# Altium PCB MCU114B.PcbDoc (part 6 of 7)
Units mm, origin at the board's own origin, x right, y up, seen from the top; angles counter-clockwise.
Board outline 105.51 x 58.76 mm, 8 copper layers (Top Layer, GND 2, Signal Layer 3, Power 4, Power 5, Signal Layer 6, GND 7, Bottom), stack 1.554 mm thick; 444 components, 418 nets, 1811 pads, 981 vias.
Unrouted connection lines stored in the file: 3.
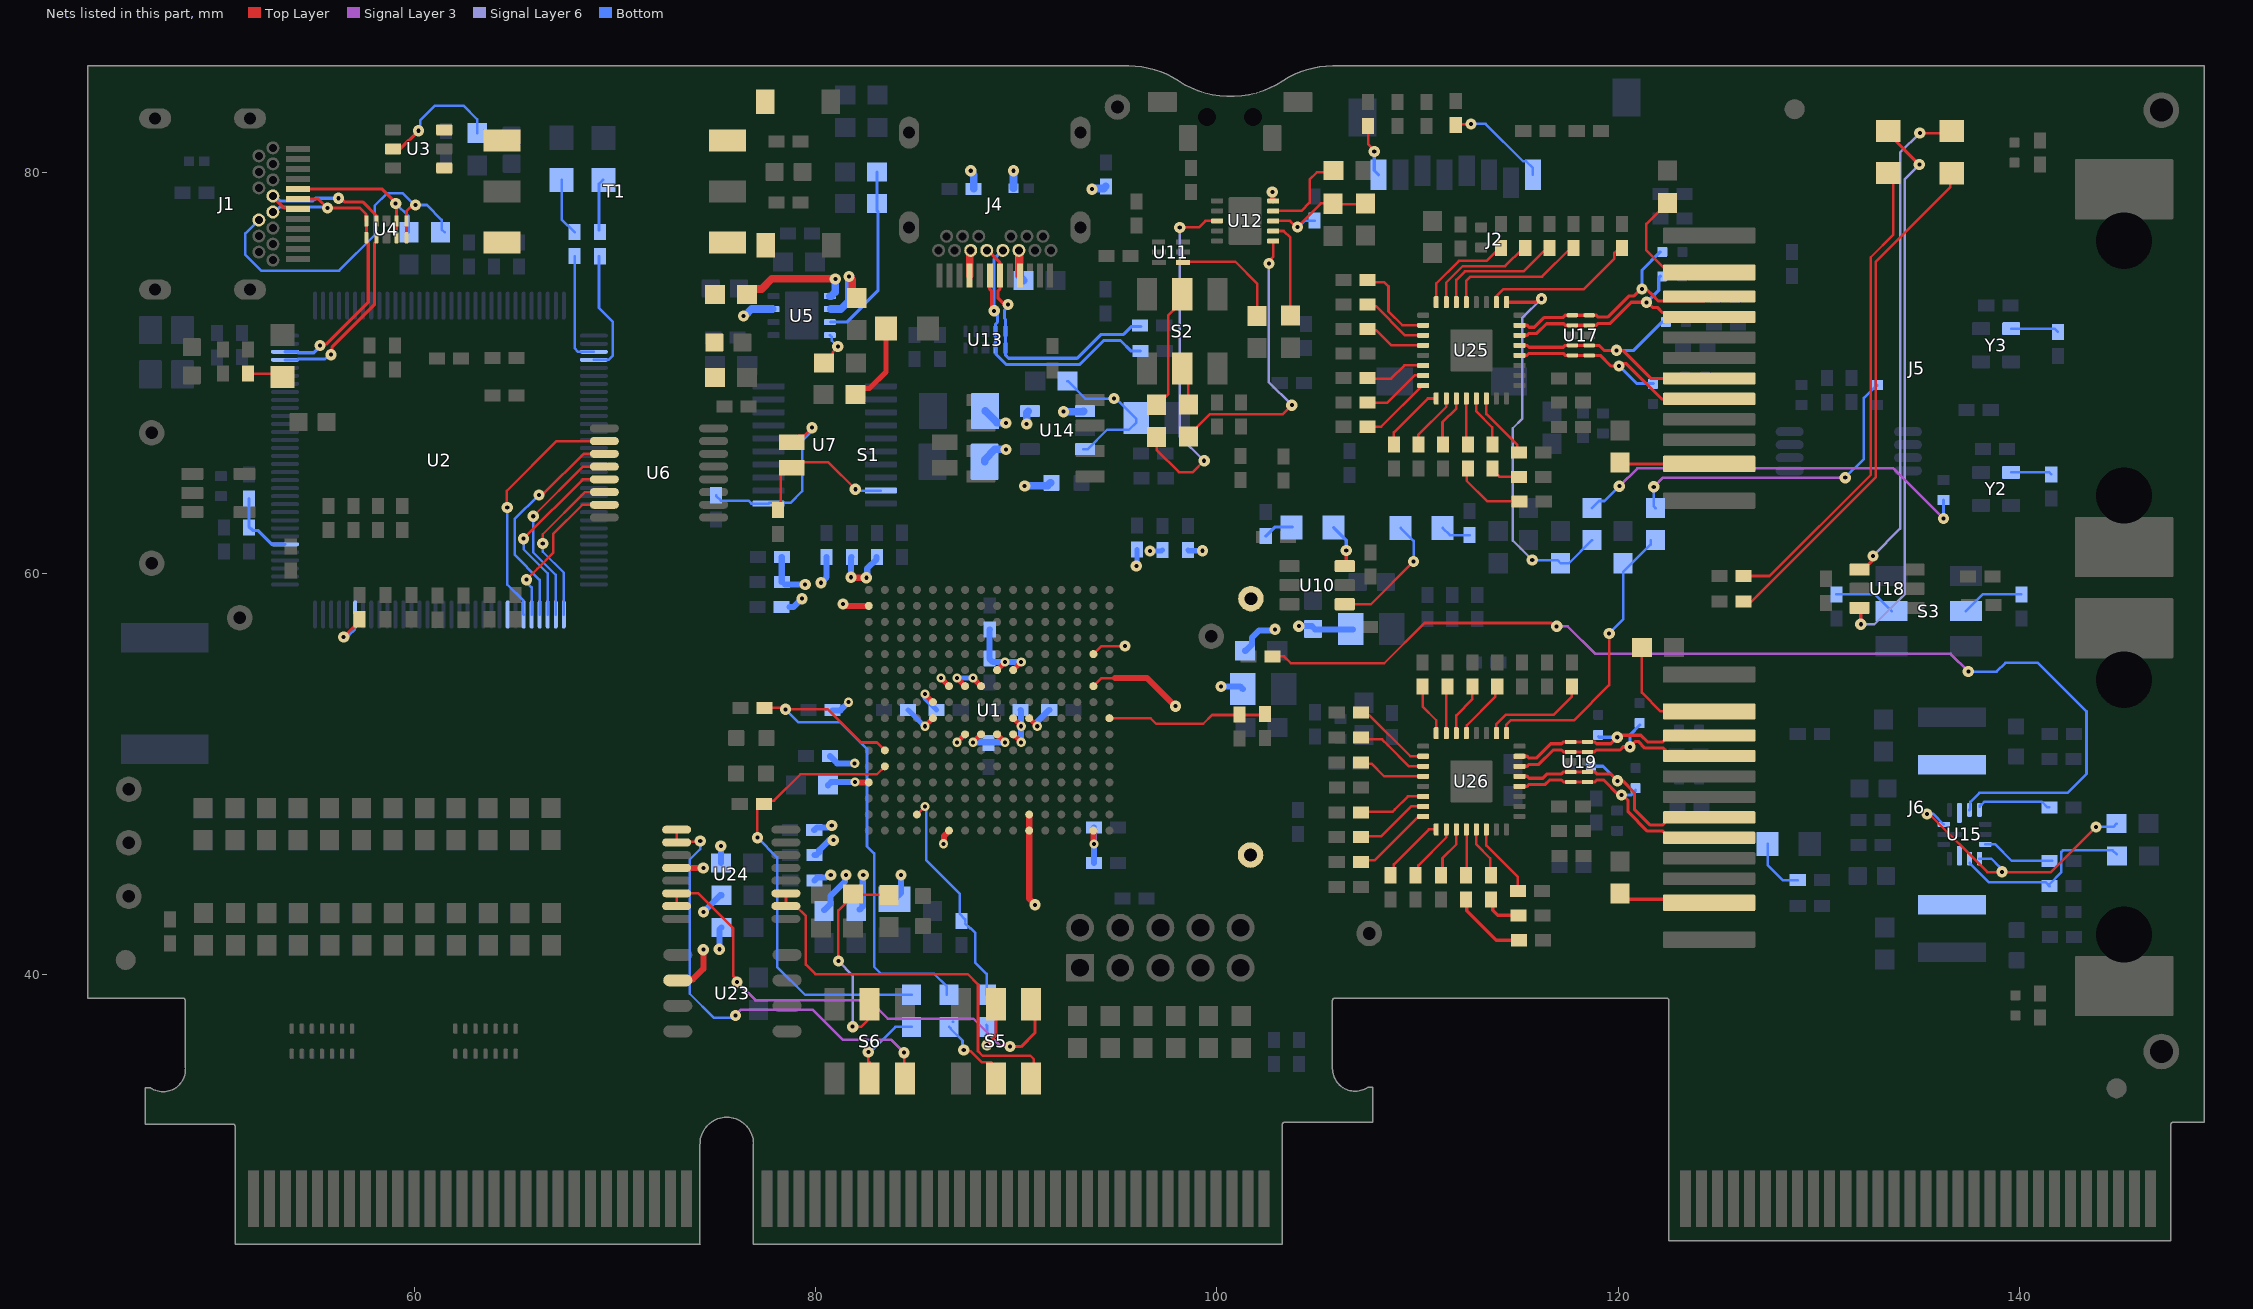
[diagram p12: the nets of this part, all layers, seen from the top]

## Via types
v1: diameter 0.559, hole 0.203, Top Layer to Bottom, tented both sides, 810 vias
v2: diameter 0.457, hole 0.203, Top Layer to Bottom, tented both sides, 153 vias
v3: diameter 0.5, hole 0.2, Top Layer to Bottom, tented both sides, 10 vias
v4: diameter 0.5, hole 0.2, Top Layer to Bottom, tented bottom, 4 vias
v5: diameter 0.5, hole 0.2, Top Layer to Bottom, tented top, 4 vias

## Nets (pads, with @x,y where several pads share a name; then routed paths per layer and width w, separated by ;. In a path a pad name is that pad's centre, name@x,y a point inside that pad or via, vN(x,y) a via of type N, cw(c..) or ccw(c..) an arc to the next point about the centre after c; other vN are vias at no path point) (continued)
NetC122_1: C122.1 R57.1 S6.5 | length 11.1
  Top Layer w0.127: v1(81.128,40.684) 81.128,43.217 81.902,43.99 C122.1@83.359,43.99 ; v1(81.839,37.414) 82.271,37.414 82.557,37.701 82.557,38.485 S6.5@82.689,38.617 ; R57.1@81.864,43.764 R57.1@81.902,43.726 ; C122.1@83.352,44.072 83.359,44.065 C122.1@83.359,43.99 ; C122.1@83.541,43.726 83.359,43.908 C122.1@83.359,43.99 ; C122.1@83.541,43.99 C122.1@83.359,43.99
  Signal Layer 6 w0.127: v1(81.128,40.684) 81.839,39.973 v1(81.839,37.414)
NetD1:A_2: D1:A.2 T1.1
NetD1_2: D1.2 R14.2 | length 1.8
  Top Layer w0.127: R14.2@51.686,69.979 53.242,69.979 D1.2@53.413,69.808
NetD2:A_2: D2:A.2 T1.3
NetD2_2: D2.2 R21.1 | length 4.2
  Top Layer w0.254: R21.1@81.978,68.937 82.284,69.242 82.679,69.242 83.497,70.06 D2.2@83.497,72.228
NetD3_1: D3.1 U10.6 | length 2.2
  Top Layer w0.159: U10.6@106.448,60.368 v1(106.448,61.155)
  Bottom w0.159: D3.1@105.822,62.298 106.448,61.672 v1(106.448,61.155)
NetD3_2: D3.2 R34.2 | length 1.5
  Bottom w0.159: R34.2@102.435,61.876 102.883,62.324 D3.2@103.756,62.324
NetD4_1: D4.1 U10.4 | length 6.3
  Top Layer w0.127: U10.4@106.375,58.478 107.678,58.478 v1(109.804,60.604)
  Bottom w0.127: D4.1@109.156,62.288 109.804,61.64 v1(109.804,60.604)
NetD4_2: D4.2 R35.2 | length 1.5
  Bottom w0.127: D4.2@111.256,62.288 111.617,61.927 R35.2@112.595,61.927
NetD5_1: D5.1 R8.1 | length 2.9
  Bottom w0.127: D5.1@67.332,79.638 67.332,77.671 R8.1@67.973,77.03
NetD6_1: D6.1 R9.1 | length 2.6
  Bottom w0.127: R9.1@69.192,77.13 69.192,79.44 D6.1@69.39,79.638
NetD7_2: D7.2 R94.1 | length 2.9
  Bottom w0.127: D7.2@127.46,46.525 127.46,45.467 128.205,44.721 R94.1@128.96,44.721
NetD8_1: D8.1 U18.6 | length 27.7
  Top Layer w0.159: U18.6@132.037,58.3 132.105,58.232 v1(132.105,57.48) ; D8.1@133.473,82.083 133.473,81.947 v1(135.022,80.398)
  Signal Layer 6 w0.127: v1(132.105,57.48) 132.78,57.48 134.298,58.998 134.298,79.674 v1(135.022,80.398)
NetD8_2: D8.2 R137.1 | length 24.1
  Top Layer w0.127: R137.1@126.265,59.885 127.553,59.885 132.599,64.932 132.599,75.779 133.731,76.911 133.731,79.725 D8.2@133.473,79.983
NetD9_1: D9.1 U18.4 | length 24.8
  Top Layer w0.127: v1(135.048,81.973) 136.542,81.973 D9.1@136.638,82.068
  Top Layer w0.159: U18.4@132.037,60.2 132.237,60.2 132.634,60.598 132.634,60.814 v1(132.711,60.891)
  Signal Layer 6 w0.127: v1(132.711,60.891) 134.07,62.25 134.07,80.995 v1(135.048,81.973)
NetD9_2: D9.2 R138.2 | length 25.9
  Top Layer w0.127: R138.2@126.251,58.615 126.651,58.615 132.859,64.824 132.859,75.557 136.575,79.273 136.575,79.906 D9.2@136.638,79.968
NetJ2_1: J2.1 R37.1 | length 5.1
  Top Layer w0.127: R37.1@111.908,82.363 111.964,82.419 v1(112.669,82.419)
  Bottom w0.127: v1(112.669,82.419) 112.68,82.43 113.4,82.43 115.264,80.566 115.421,80.566 115.757,80.229 J2.1@115.757,79.893
NetJ2_8: J2.8 R43.2 | length 2.6
  Top Layer w0.127: R43.2@107.54,82.323 107.54,81.419 107.844,81.115 v1(107.844,81.058)
  Bottom w0.159: v1(107.844,81.058) 107.844,80.106 J2.8@108.057,79.893
NetJ5_2: J5.2 R135.2 | length 6.4
  Top Layer w0.127: R135.2@122.463,78.494 121.412,77.443 121.412,76.124 122.517,75.018 J5.2@124.544,75.018
NetJ5_11: J5.11 R132.2 | length 4.5
  Top Layer w0.159: R132.2@120.057,65.847 R132.2@120.115,65.905 ; R132.2@120.102,65.537 120.161,65.478 J5.11@124.544,65.478
NetJ6_2: J6.2 R169.2 | length 6
  Top Layer w0.127: R169.2@121.192,56.319 121.192,54.068 122.128,53.132 J6.2@124.544,53.132
NetJ6_11: J6.11 R167.2 | length 4.6
  Top Layer w0.159: R167.2@120.102,44.048 120.38,43.771 124.365,43.771 J6.11@124.544,43.592
NetL1_1: L1.1 U15.6
NetL2_1: L2.1 U15.12
NetR1_1: R1.1 S1.1 U7.1 | length 9.4
  Top Layer w0.127: S1.1@78.8,66.555 79.116,66.871 79.404,66.871 v1(79.814,67.282)
  Bottom w0.127: R1.1@75.034,63.911 75.034,63.876 75.271,63.64 76.644,63.64 76.788,63.496 U7.1@77.642,63.496 77.676,63.531 78.736,63.531 79.324,64.119 79.324,66.623 79.814,67.113 v1(79.814,67.282)
NetR8_2: R8.2 U2.3 | length 5.6
  Bottom w0.127: R8.2@67.973,75.83 67.973,71.245 68.152,71.066 U2.3@68.935,71.066
NetR9_2: R9.2 U2.4 | length 6.3
  Bottom w0.127: U2.4@68.935,70.666 69.657,70.666 69.883,70.891 69.883,72.56 69.192,73.251 R9.2@69.192,75.83
NetR10_1: R10.1 R11.2 U2.70 | length 3.6
  Bottom w0.159: R10.1@51.737,63.756 51.737,62.349 51.928,62.158 52.182,62.158 52.866,61.473 53.528,61.473 U2.70@53.535,61.466
NetR12_2: R12.2 U2.59 | length 2.7
  Top Layer w0.159: v1(56.46,56.852) 56.476,56.852 57.254,57.63 R12.2@57.254,57.73
  Bottom w0.127: v1(56.46,56.852) 56.543,56.935 56.735,56.935 57.022,57.222 57.022,57.952 U2.59@57.035,57.966
NetR18_1: R18.1 U3.5 | length 6.3
  Top Layer w0.159: U3.5@58.925,81.18 59.29,81.18 v1(60.195,82.085)
  Bottom w0.127: v1(60.195,82.085) 60.271,82.161 60.271,82.597 61.012,83.337 62.437,83.337 63.121,82.653 R18.1@63.121,81.964
NetR19_1: R19.1 U5.1 | length 5.7
  Top Layer w0.381: R19.1@76.568,73.914 76.85,74.196 77.308,74.196 77.813,74.701 v1(80.975,74.701)
  Bottom w0.381: U5.1@80.699,73.843 80.768,73.843 80.975,74.05 v1(80.975,74.701)
NetR24_1: R24.1 R26.2 U5.3 | length 8.9
  Bottom w0.159: U5.3@80.75,72.548 81.54,72.548 83.096,74.104 83.096,78.066 83.046,78.116 R24.1@83.046,80.033
NetR25_2: R25.2 U5.4 | length 1.9
  Top Layer w0.127: R25.2@80.404,70.51 80.429,70.51 80.84,70.922 80.84,71.036 81.098,71.293 v1(81.098,71.326)
  Bottom w0.127: U5.4@80.699,71.893 80.711,71.893 80.797,71.806 80.797,71.626 v1(81.098,71.326)
NetR27_2: R27.2 U5.2 | length 3.6
  Top Layer w0.381: v1(81.659,74.818) 81.813,74.664 81.813,73.927 R27.2@82.042,73.698
  Bottom w0.381: U5.2@80.75,73.198 81.238,73.198 81.659,73.618 v1(81.659,74.818)
NetR33_1: R33.1 S2.2 | length 6
  Top Layer w0.127: R33.1@97.039,68.407 97.582,68.95 97.582,72.893 97.836,73.147 97.836,73.499 S2.2@98.273,73.935
NetR33_2: R33.2 U12.3 | length 17.8
  Top Layer w0.127: R33.2@96.998,66.825 96.998,66.171 98.1,65.069 98.8,65.069 v1(99.365,65.634) ; v1(98.146,77.267) 99.101,77.267 99.423,77.589 U12.3@100.008,77.589
  Signal Layer 6 w0.127: v1(98.146,77.267) 98.146,66.853 v1(99.365,65.634)
NetR44_2: R44.2 U11.4 | length 5.8
  Top Layer w0.127: U11.4@98.308,75.529 98.308,75.559 100.914,75.559 102.006,74.467 R44.2@102.006,72.86
NetR46_2: R46.2 R48.2 U1.J16 | length 8.1
  Top Layer w0.127: U1.J16@94.641,52.795 96.691,52.795 96.965,52.521 99.318,52.521 99.754,52.957 102.344,52.957 R46.2@102.387,53
NetR49_2: R49.2 U12.9 | length 4.6
  Top Layer w0.127: U12.9@102.808,78.089 104.212,78.089 104.623,78.5 104.623,79.649 104.991,80.017 R49.2@105.901,80.017
NetR52_1: R52.1 U12.6 | length 14.6
  Top Layer w0.127: R52.1@98.6,66.832 98.6,66.909 99.635,67.945 103.276,67.945 v1(103.734,68.402) ; v1(102.591,75.463) 102.591,75.58 102.808,75.798 U12.6@102.808,76.589
  Signal Layer 6 w0.127: v1(102.591,75.463) 102.583,75.456 102.583,69.553 v1(103.734,68.402)
NetR52_2: R52.2 S2.5 | length 1.9
  Top Layer w0.127: S2.5@98.273,70.235 98.577,69.93 R52.2@98.577,68.44
NetR53_1: R53.1 U15.4 U15.10 | length 14.4
  Top Layer w0.127: v1@135.241,48.023 v1(135.403,48.023) 135.517,48.023 138.417,45.124 141.582,45.124 v1(143.836,47.378)
  Bottom w0.127: v1(135.403,48.023) 135.719,48.023 U15.10@136.235,47.507 ; U15.4@138.023,45.795 138.608,45.795 138.999,45.404 138.999,45.395 139.27,45.124 v1@139.279,45.124 ; v1(143.836,47.378) 144.694,47.378 R53.1@144.855,47.539
  other v1: 139.141,45.136
NetR55_2: R55.2 R61.1 R78.2 U12.8 | length 6.2
  Top Layer w0.127: U12.8@102.808,77.589 103.645,77.589 103.942,77.292 v1(104.013,77.292) 105.183,78.462 R78.2@105.835,78.462 ; R78.2@105.871,78.429 R55.2@107.471,78.429
  Bottom w0.127: v1(104.013,77.292) 104.084,77.292 104.381,77.589 104.859,77.589 R61.1@104.877,77.607
NetR58_1: R58.1 U25.23 | length 3.4
  Top Layer w0.127: R58.1@107.494,68.53 108.503,68.53 109.861,69.887 U25.23@110.285,69.887
NetR62_2: R62.2 S3.2 | length 3.1
  Bottom w0.127: S3.2@137.345,58.133 138.181,58.969 R62.2@140.106,58.969
NetR63_2: R63.2 S3.5 | length 3.1
  Bottom w0.127: R63.2@130.885,58.969 132.808,58.969 S3.5@133.645,58.133
NetR69_1: R69.1 Y2.1 | length 2
  Bottom w0.127: Y2.1@139.602,65.054 141.502,65.054 R69.1@141.601,64.955
NetR76_1: R76.1 Y3.1 | length 2.4
  Bottom w0.127: Y3.1@139.602,72.216 141.772,72.216 R76.1@141.931,72.057
NetR82_1: R82.1 U15.13 | length 53.7
  Top Layer w0.127: R82.1@102.78,55.88 103.35,55.88 103.693,55.537 108.344,55.537 110.35,57.544 116.66,57.544 116.825,57.379 v1(116.942,57.379)
  Signal Layer 3 w0.127: v1(116.942,57.379) 117.494,57.379 118.866,56.007 125.891,56.007 125.897,56.001 126.265,56.001 126.271,56.007 136.576,56.007 v1(137.465,55.118)
  Bottom w0.127: v1(137.465,55.118) 138.877,55.118 139.317,55.558 140.937,55.558 143.358,53.136 143.358,50.013 142.418,49.073 138.017,49.073 137.568,48.623 137.568,48.265 U15.13@137.523,48.22
NetR83_1: R83.1 U25.27 | length 2.6
  Top Layer w0.127: R83.1@111.247,66.454 111.247,67.559 111.935,68.247 U25.27@111.935,68.737
NetR84_1: R84.1 U25.26 | length 2.9
  Top Layer w0.127: R84.1@110.036,66.454 110.036,66.916 111.435,68.315 U25.26@111.435,68.737
NetR86_1: R86.1 U25.25 | length 3.4
  Top Layer w0.127: R86.1@108.825,66.454 108.825,67.042 110.52,68.737 U25.25@110.935,68.737
NetR87_1: R87.1 U25.24 | length 3.6
  Top Layer w0.127: R87.1@107.494,67.327 108.19,67.327 110.25,69.387 U25.24@110.285,69.387
NetR91_1: R91.1 U26.23 | length 3.7
  Top Layer w0.127: R91.1@107.161,46.917 108.201,46.917 108.325,47.041 109.683,48.399 U26.23@110.285,48.399
NetR92_1: R92.1 U26.27 | length 2.6
  Top Layer w0.127: R92.1@111.247,44.966 111.247,45.823 111.935,46.511 U26.27@111.935,47.249
NetR97_1: R97.1 U15.3 | length 3.7
  Bottom w0.127: U15.3@138.31,46.507 138.811,46.507 139.632,45.687 R97.1@141.658,45.687
NetR100_1: R100.1 S1.2 U7.19 | length 8.8
  Top Layer w0.127: R100.1@78.105,63.186 78.261,63.341 78.261,64.968 78.293,65.001 78.336,65.001 78.62,65.285 S1.2@78.8,65.285 78.685,65.285 78.653,65.252 S1.2@78.369,64.968 ; S1.2@78.302,65.039 78.584,65.321 78.817,65.554 80.628,65.554 v1(81.971,64.211)
  Bottom w0.127: v1(81.971,64.211) 82.036,64.146 U7.19@83.242,64.146
NetR103_1: R103.1 R104.2 U15.5 | length 9.2
  Bottom w0.127: U15.5@137.528,45.577 138.477,44.628 141.31,44.628 141.464,44.474 R103.1@141.513,44.425 ; R103.1@141.508,44.518 142.108,45.118 142.108,46.135 142.183,46.209 144.663,46.209 R104.2@144.855,46.017
NetR109_2: R109.2 U25.10 | length 7.6
  Top Layer w0.127: U25.10@113.935,73.537 113.935,73.84 114.27,74.175 118.284,74.175 119.821,75.712 119.821,76.001 R109.2@120.036,76.216
NetR110_1: R110.1 U26.26 | length 2.9
  Top Layer w0.127: R110.1@110.044,44.966 110.044,45.458 111.435,46.85 U26.26@111.435,47.249
NetR114_2: R114.2 U25.19 | length 3.4
  Top Layer w0.127: R114.2@107.494,73.339 107.934,73.339 109.385,71.887 U25.19@110.285,71.887
NetR115_2: R115.2 U25.18 | length 4.4
  Top Layer w0.127: R115.2@107.494,74.541 108.342,74.541 108.556,74.327 108.556,73.082 109.251,72.387 U25.18@110.285,72.387
NetR116_2: R116.2 U25.15 | length 5.5
  Top Layer w0.127: U25.15@111.435,73.537 111.435,74.515 112.257,75.337 114.373,75.337 R116.2@115.252,76.216
NetR117_2: R117.2 U25.14 | length 6.3
  Top Layer w0.127: U25.14@111.935,73.537 111.935,74.647 112.365,75.077 115.295,75.077 R117.2@116.435,76.216
NetR118_2: R118.2 U25.13 | length 6.9
  Top Layer w0.127: U25.13@112.435,73.537 112.435,74.614 112.638,74.816 116.218,74.816 R118.2@117.618,76.216
NetR119_2: R119.2 U25.20 | length 3.1
  Top Layer w0.127: R119.2@107.494,72.136 107.949,72.136 108.698,71.387 U25.20@110.285,71.387
NetR120_2: R120.2 U25.22 | length 3.1
  Top Layer w0.127: R120.2@107.494,69.732 108.689,69.732 109.345,70.387 U25.22@110.285,70.387
NetR121_1: R121.1 R123.2 | length 3.6
  Top Layer w0.127: R121.1@112.458,65.254 112.458,64.634 113.473,63.619 R123.2@115.006,63.619
NetR121_2: R121.2 U25.28 | length 2.3
  Top Layer w0.127: U25.28@112.435,68.737 112.435,66.477 R121.2@112.458,66.454
NetR122_1: R122.1 R124.2 | length 1.5
  Top Layer w0.127: R122.1@113.669,65.254 114.085,64.838 R124.2@114.981,64.838
NetR122_2: R122.2 U25.29 | length 2.6
  Top Layer w0.127: U25.29@112.935,68.737 112.935,68.093 113.727,67.302 113.727,66.512 R122.2@113.669,66.454
NetR125_2: R125.2 U25.30 | length 3.3
  Top Layer w0.127: U25.30@113.435,68.737 113.435,67.959 114.787,66.607 114.981,66.414 R125.2@114.981,66.057
NetR126_2: R126.2 U25.16 | length 4.8
  Top Layer w0.127: U25.16@110.935,73.537 110.935,74.472 112.061,75.597 113.45,75.597 R126.2@114.069,76.216
NetR143_2: R143.2 U26.10 | length 5.3
  Top Layer w0.127: U26.10@113.935,52.049 113.935,52.504 114.397,52.966 116.785,52.966 117.699,53.88 R143.2@117.699,54.372
NetR144_1: R144.1 U26.25 | length 3.4
  Top Layer w0.127: R144.1@108.825,44.966 108.827,44.968 108.827,45.511 110.565,47.249 U26.25@110.935,47.249
NetR148_2: R148.2 U26.19 | length 3.7
  Top Layer w0.127: R148.2@107.161,51.736 108.237,51.736 108.517,51.455 109.573,50.399 U26.19@110.285,50.399
NetR149_2: R149.2 U26.18 | length 4
  Top Layer w0.127: R149.2@107.161,52.94 107.606,52.94 109.648,50.899 U26.18@110.285,50.899
NetR150_2: R150.2 U26.15 | length 2.3
  Top Layer w0.127: U26.15@111.435,52.049 111.435,54.31 R150.2@111.497,54.372
NetR151_1: R151.1 U26.30 | length 3.7
  Top Layer w0.127: U26.30@113.435,47.224 113.435,46.447 115.006,44.876 R151.1@115.006,44.188
NetR152_2: R152.2 U26.14 | length 2.7
  Top Layer w0.127: U26.14@111.935,52.049 111.935,52.94 112.738,53.743 R152.2@112.738,54.372
NetR153_2: R153.2 U26.13 | length 3
  Top Layer w0.127: U26.13@112.435,52.049 112.457,52.071 112.457,52.438 113.876,53.856 113.876,54.27 R153.2@113.978,54.372
NetR154_2: R154.2 U26.20 | length 3.4
  Top Layer w0.127: R154.2@107.161,50.531 107.711,50.531 108.339,49.903 110.281,49.903 U26.20@110.285,49.899
NetR155_2: R155.2 U26.22 | length 3.4
  Top Layer w0.127: R155.2@107.161,48.122 108.745,48.122 108.867,48.244 109.522,48.899 U26.22@110.285,48.899
NetR156_1: R156.1 R159.2 | length 3.8
  Top Layer w0.159: R156.1@112.458,43.766 112.458,43.196 113.93,41.724 R159.2@115.057,41.724
NetR156_2: R156.2 U26.28 | length 2.3
  Top Layer w0.127: U26.28@112.435,47.249 112.458,47.227 R156.2@112.458,44.966
NetR157_1: R157.1 R160.2 | length 2
  Top Layer w0.159: R157.1@113.669,43.766 113.754,43.68 113.754,43.221 114.006,42.969 R160.2@115.032,42.969
NetR157_2: R157.2 U26.29 | length 2.6
  Top Layer w0.127: U26.29@112.935,47.249 112.935,46.503 113.625,45.814 113.625,45.01 R157.2@113.669,44.966
NetR158_2: R158.2 U26.16 | length 2.6
  Top Layer w0.127: R158.2@110.257,54.372 110.257,53.373 110.935,52.694 U26.16@110.935,52.049
NetR171_2: R171.2 U15.14 | length 3.7
  Bottom w0.127: U15.14@138.024,48.384 138.024,48.434 138.084,48.494 138.134,48.494 138.277,48.637 141.125,48.637 141.408,48.354 R171.2@141.508,48.354
NetR196_1: R196.1 S6.2 | length 4.7
  Top Layer w0.127: v1(82.62,36.152) 82.62,34.986 82.689,34.917 82.689,35.65
  Bottom w0.127: v1(82.62,36.152) 82.718,36.152 83.974,37.408 R196.1@84.781,37.408
NetR196_2: R196.2 R199.2 U1.M2 | length 22.8
  Top Layer w0.127: v1(77.089,46.838) 77.089,48.278 77.325,48.514 R199.2@77.41,48.514 77.586,48.69 77.926,48.69 79.236,50.001 83.047,50.001 U1.M2@83.441,50.395
  Bottom w0.127: v1(77.089,46.838) 78.077,45.85 78.077,40.397 79.465,39.008 R196.2@84.781,39.008
NetR197_1: R197.1 S5.5 | length 3.4
  Top Layer w0.155: v1(88.534,36.507) 88.986,36.959 88.986,38.422 S5.5@89.181,38.617
  Bottom w0.155: R197.1@88.515,37.492 88.534,37.473 v1(88.534,36.507)
NetR197_2: R197.2 R200.2 U1.R4 | length 11.1
  Top Layer w0.127: U1.R4@85.041,47.995 v2(85.441,48.395)
  Bottom w0.127: v2(85.441,48.395) 85.498,48.338 85.498,45.72 87.169,44.05 87.169,43.049 87.448,42.769 R200.2@87.448,42.669 ; R200.2@87.448,42.569 87.684,42.333 87.71,42.333 87.956,42.087 87.956,40.924 87.956,40.6 88.515,40.042 R197.2@88.515,39.008
NetR198_1: R198.1 S5.2 | length 4
  Top Layer w0.127: v1(87.376,36.246) 87.434,36.188 87.729,36.188 88.264,35.653 88.744,35.653 89.181,35.217 S5.2@89.181,34.917
  Bottom w0.127: R198.1@86.648,37.408 86.718,37.338 86.718,37.313 87.316,36.716 87.316,36.306 v1(87.376,36.246) ; R198.1@86.836,37.658 R198.1@86.842,37.653
NetR198_2: R198.2 R201.2 U1.L2 | length 27.2
  Top Layer w0.127: R201.2@77.439,53.308 78.399,53.308 78.469,53.238 80.598,53.238 82.251,51.585 83.051,51.585 U1.L2@83.441,51.195
  Bottom w0.127: v1(78.486,53.238) 79.14,52.585 81.231,52.585 82.553,51.263 82.553,46.403 82.906,46.05 82.906,40.405 83.255,40.056 85.905,40.056 86.534,39.427 R198.2@86.534,39.008
NetR203_1: R203.1 U26.24 | length 4
  Top Layer w0.127: R203.1@107.161,45.712 107.86,45.712 108.52,46.372 110.046,47.899 U26.24@110.285,47.899
NetR212_2: R212.2 U12.7 | length 4.9
  Top Layer w0.127: U12.7@102.808,77.089 103.327,77.089 103.658,76.758 R212.2@103.658,72.867
NetS5_3: S5.3 U24.10 U24.11 | length 20.4
  Top Layer w0.127: U24.11@78.514,44.063 U24.10@78.514,43.428 79.001,43.428 79.501,42.928 79.501,40.514 79.976,40.039 87.578,40.039 88.089,39.528 88.089,36.193 88.316,35.966 90.703,35.966 90.878,35.792 S5.3@90.878,34.97
NetS5_6: S5.6 U24.6 U24.7 | length 25
  Top Layer w0.127: U24.7@73.064,43.428 U24.6@73.064,44.063 74.151,44.063 75.895,42.319 75.895,39.94 76.073,39.762 v1(76.073,39.649) ; U24.7@73.09,43.352 U24.7@73.09,43.428
  Top Layer w0.159: v1(89.687,36.424) 90.238,36.424 90.931,37.116 S5.6@90.931,38.617
  Signal Layer 3 w0.127: v1(76.073,39.649) 76.987,38.735 82.677,38.735 83.601,37.811 87.858,37.811 89.218,36.451 89.66,36.451 v1(89.687,36.424)
NetS6_3: S6.3 U24.1 U24.2 | length 23.2
  Top Layer w0.127: U24.1@73.064,47.238 U24.2@73.064,46.603 73.096,46.635 74.208,46.635 v1(74.239,46.667) ; S6.3@84.244,34.85 84.404,35.01 v1(84.404,36.119)
  Signal Layer 3 w0.127: v1(75.993,37.98) 76.279,38.266 79.663,38.266 79.664,38.266 79.844,38.266 81.356,36.754 83.769,36.754 v1(84.404,36.119)
  Bottom w0.127: v1(74.239,46.667) 74.239,46.27 73.717,45.748 73.717,39.059 74.923,37.852 75.748,37.852 75.876,37.98 v1(75.993,37.98)
NetT1_4: T1.4 U3.3
NetT1_6: T1.6 U3.1
PHY0_25MHZ_CLK: R60.2 R67.2 | length 20.3
  Signal Layer 3 w0.132: v1(120.066,64.364) 120.959,65.257 133.73,65.257 v1(136.231,62.755)
  Bottom w0.132: R60.2@118.706,63.276 119.053,63.623 119.325,63.623 v1(120.066,64.364) ; v1(136.231,62.755) R67.2@136.231,63.678
PHY0_CLK: R59.2 R60.1 U25.9 | length 19.4
  Top Layer w0.159: U25.9@114.435,73.537 115.898,73.537 116.071,73.711 v1(116.18,73.711)
  Signal Layer 6 w0.127: v1(115.722,60.681) 114.75,61.653 114.75,67.254 115.234,67.738 115.234,72.765 v1(116.18,73.711)
  Bottom w0.127: v1(115.722,60.681) 116.982,60.681 R59.2@117.142,60.521 117.551,60.521 R60.1@118.706,61.676
PHY0_RD_N: C93.1 J5.8 U17.5 U17.6 U25.4 | length 12.6
  Top Layer w0.157: U25.4@115.085,70.887 115.462,70.887 115.559,70.985 117.269,70.985 117.367,70.887 U17.5@117.725,70.887 U17.6@118.56,70.887 119.115,70.887 119.645,70.357 v1(120.051,70.357) ; v1@120.043,70.434 120.086,70.477 120.407,70.477 122.165,68.718 J5.8@124.544,68.718
  Bottom w0.157: v1(120.051,70.357) 120.927,69.482 C93.1@121.754,69.482
PHY0_RD_P: C94.1 J5.7 U17.4 U17.7 U25.5 | length 13.2
  Top Layer w0.157: U25.5@115.085,71.387 115.462,71.387 115.559,71.29 117.269,71.29 117.367,71.387 U17.4@117.725,71.387 U17.7@118.56,71.387 119.053,71.387 119.303,71.137 v1(119.924,71.137) 120.231,71.137 121.63,69.738 J5.7@124.544,69.738
  Bottom w0.157: v1(119.924,71.137) 120.78,71.137 121.964,72.321 122.185,72.542 C94.1@122.285,72.542
PHY0_TD_N: C91.1 J5.4 U17.2 U17.9 U25.6 | length 12.1
  Top Layer w0.157: U25.6@115.085,71.887 115.464,71.887 115.559,71.982 115.952,71.982 116.431,72.461 117.291,72.461 117.364,72.387 U17.2@117.725,72.387 U17.9@118.56,72.387 118.922,72.387 119.017,72.482 119.61,72.482 120.659,73.532 v1(121.426,73.532) 121.466,73.532 121.719,73.279 121.954,73.279 122.208,73.025 124.318,73.025 J5.4@124.544,72.798
  Bottom w0.157: v1(121.426,73.532) 122.029,74.134 122.029,74.75 C91.1@122.107,74.828
PHY0_TD_P: C92.1 J5.3 U17.1 U17.10 U25.7 | length 13.2
  Top Layer w0.157: U25.7@115.085,72.387 115.464,72.387 115.559,72.292 115.824,72.292 116.303,72.771 117.248,72.771 117.364,72.887 U17.1@117.725,72.887 U17.10@118.56,72.887 118.922,72.887 119.017,72.792 119.482,72.792 120.531,73.842 120.777,73.842 121.125,74.189 v1(121.193,74.189) 121.419,74.189 121.724,73.884 122.016,73.592 124.318,73.592 J5.3@124.544,73.818
  Bottom w0.157: v1@121.028,74.033 v1@121.188,74.194 ; v1(121.193,74.189) 121.193,75.133 C92.1@122.107,76.048
PHY1_25MHZ_CLK: R66.2 R68.2 | length 16.1
  Signal Layer 3 w0.132: v1(121.782,64.334) 122.238,64.79 v1(131.328,64.79)
  Bottom w0.132: v1(121.782,64.334) 121.782,63.358 R66.2@121.869,63.271 ; v1(131.328,64.79) 132.258,65.72 132.258,68.76 R68.2@132.904,69.406 R68.2@132.923,69.387
PHY1_CLK: R64.2 R66.1 U26.9 | length 14.5
  Top Layer w0.127: U26.9@114.435,52.049 114.435,52.479 114.661,52.705 117.819,52.705 119.558,54.443 v1(119.558,57.023)
  Bottom w0.127: v1(119.558,57.023) 120.255,57.72 120.255,60.076 121.626,61.447 R66.1@121.626,61.676
PHY1_RD_N: C109.1 J6.8 U19.5 U19.6 U26.4 | length 12
  Top Layer w0.157: U26.4@115.085,49.399 115.464,49.399 115.559,49.494 116.379,49.494 116.597,49.713 117.185,49.713 117.28,49.618 U19.5@117.641,49.618 U19.6@118.476,49.618 118.838,49.618 118.933,49.713 119.287,49.713 120.036,48.963 v1(120.178,48.963) 120.231,48.963 120.504,48.69 120.504,48.125 121.461,47.168 122.23,47.168 122.323,47.076 122.323,47.059 122.549,46.832 J6.8@124.544,46.832
  Bottom w0.157: v1(120.178,48.963) 120.632,48.963 C109.1@120.879,49.209
PHY1_RD_P: C110.1 J6.7 U19.4 U19.7 U26.5 | length 12.9
  Top Layer w0.157: U26.5@115.085,49.899 115.464,49.899 115.559,49.804 116.25,49.804 116.469,50.023 117.185,50.023 117.28,50.118 U19.4@117.641,50.118 U19.7@118.476,50.118 118.838,50.118 118.933,50.023 119.627,50.023 v1(119.975,49.674) 120.231,49.674 120.814,49.092 120.814,48.254 121.59,47.478 122.23,47.478 122.323,47.57 122.323,47.626 122.549,47.852 J6.7@124.544,47.852
  Bottom w0.157: C110.1@118.743,50.399 119.251,50.399 v1(119.975,49.674)
PHY1_TD_N: C107.1 J6.4 U19.2 U19.9 U26.6 | length 10.9
  Top Layer w0.157: U26.6@115.085,50.399 115.464,50.399 115.559,50.494 116.054,50.494 116.773,51.213 117.185,51.213 117.28,51.118 U19.2@117.641,51.118 U19.9@118.476,51.118 118.485,51.126 118.821,51.126 118.908,51.213 120.106,51.213 120.263,51.37 v1(120.603,51.37) 120.871,51.638 121.006,51.638 121.341,51.303 122.261,51.303 J6.4@122.373,51.19 ; J6.4@122.997,50.912 J6.4@124.544,50.912
  Bottom w0.157: v1(120.603,51.37) 120.603,51.978 C107.1@121.08,52.455
PHY1_TD_P: C108.1 J6.3 U19.1 U19.10 U26.7 | length 9
  Top Layer w0.157: U26.7@115.085,50.899 115.464,50.899 115.559,50.804 115.926,50.804 116.644,51.523 117.185,51.523 117.28,51.618 U19.1@117.641,51.618 U19.10@118.476,51.618 118.485,51.609 118.84,51.609 118.927,51.523 119.634,51.523 v1(119.96,51.848) 120.06,51.948 121.134,51.948 121.469,51.613 122.23,51.613 122.323,51.705 122.357,51.741 J6.3@122.373,51.741
  Bottom w0.157: C108.1@119.026,51.883 119.061,51.848 v1(119.96,51.848)
POWER_SWITCH_OUT: C26.2 R19.2 R20.2 U5.7 | length 1.6
  Bottom w0.381: v1(76.403,72.847) 76.451,72.847 76.804,73.2 U5.7@77.84,73.2
USB-PFLT: R85.1 R90.1 U14.3 | length 7.6
  Bottom w0.127: R90.1@92.542,69.602 92.567,69.602 93.436,68.732 94.96,68.732 95.982,67.711 95.982,67.545 95.614,67.177 94.523,67.177 93.545,66.2 U14.3@93.345,66.2
  other v1: 94.869,68.732
USB_5V0: C46.1 C47.1 R93.1 U14.5 | length 4.1
  Bottom w0.381: C47.1@88.422,65.583 88.422,65.689 88.932,66.199 v1(89.489,66.199) ; C46.1@88.444,68.115 89.038,67.521 v1(89.476,67.521) ; v1(90.514,67.462) 90.514,68.019 U14.5@90.595,68.1 ; v1(93.777,79.172) 93.811,79.206 94.357,79.206 R93.1@94.463,79.311
USB_D_N: J4.A7 J4.B7 R81.1 U13.2 U13.9 | length 15.2
  Top Layer w0.155: J4.A7@88.675,74.866 88.675,74.188 88.772,74.092 v1@88.772,73.334
  Bottom w0.155: J4.B7@89.325,76.126 88.896,75.696 v1(88.896,73.107) 89.057,72.946 89.057,72.541 88.96,72.445 U13.9@88.96,72.085 U13.2@88.96,71.25 88.983,71.228 88.983,70.936 89.482,70.436 93.161,70.436 93.251,70.526 94.353,71.628 95.193,71.628 95.722,71.099 R81.1@96.199,71.099
USB_D_P: J4.A6 J4.B6 R80.1 U13.1 U13.10 | length 13.4
  Top Layer w0.155: J4.B6@88.525,76.126 88.577,76.126 89.175,75.527 J4.A6@89.175,74.866 89.175,74.188 89.079,74.092 89.079,73.756 89.417,73.417 v1(89.577,73.417)
  Bottom w0.155: v1(89.577,73.417) 89.577,73.308 89.411,73.142 89.411,72.729 89.46,72.68 U13.10@89.46,72.085 U13.1@89.46,71.25 89.468,71.243 89.468,70.886 89.609,70.744 93.034,70.744 94.225,71.935 95.348,71.935 95.732,72.319 R80.1@96.209,72.319
VBUS_5V0: C44.1 C45.2 J4.A4 J4.A9 J4.B4 J4.B9 R77.2 R79.2 U14.1 | length 8.4
  Top Layer w0.381: J4.A9@87.675,74.866 87.675,76.076 J4.B4@87.725,76.126 ; J4.B9@90.125,76.126 90.175,76.076 J4.A4@90.175,74.866
  Bottom w0.381: v1(87.727,80.093) 87.727,80.024 87.869,79.883 R77.2@87.869,79.189 ; C44.1@89.862,79.215 v1@89.861,80.092 ; J4.B9@90.125,76.126 90.125,74.851 R79.2@90.356,74.621 ; v1(90.417,64.38) 91.551,64.38 C45.2@91.704,64.533 ; v1(92.35,68.079) 93.324,68.079 U14.1@93.345,68.1
  other v1: 89.861,80.093
VDD_1V2: C55.1 C56.1 C57.1 C58.1 C59.1 C60.1 C61.1 C85.2 L5.2 TP7.1 U1.F9 U1.F10 U1.G6 U1.J11 U1.K8 U1.K9 U12.10 | length 14.4
  Top Layer w0.254: v2(86.241,54.795) U1.G6@86.641,54.395 ; v2(87.841,51.595) U1.K8@88.241,51.995 ; U1.K9@89.041,51.995 v2(89.441,51.595) ; U1.F9@89.041,55.195 v2(89.441,55.595) ; U1.F10@89.841,55.195 v2(90.241,55.595) ; U1.J11@90.641,52.795 v2(91.041,52.395) ; v1(102.764,79.026) 102.786,79.004 102.786,78.591 102.788,78.589 U12.10@102.808,78.589
  Bottom w0.254: v1@96.012,60.548 C57.1@96.012,61.198 ; v1(96.667,61.139) 97.241,61.139 C59.1@97.283,61.182 ; C60.1@98.554,61.187 98.596,61.145 v1(99.284,61.145)
  Bottom w0.305: v2(87.841,51.595) v2(89.441,51.595) ; C55.1@88.674,57.212 88.66,57.198 C56.1@88.66,55.769 88.834,55.595 v2(89.441,55.595) v2(90.241,55.595) ; v2(91.041,52.395) 91.041,52.614 C58.1@91.641,53.214 ; v1(104.085,57.385) 104.732,57.385 104.899,57.218 L5.2@106.778,57.218
  other v1: 95.982,60.383
VDDA_3V3: C32.1 C33.1 C62.1 C67.1 C120.1 C124.1 L4.2 U1.N1 U1.T6 U23.2 U24.4 | length 15.2
  Top Layer w0.305: U24.4@73.064,45.333 v1@74.38,45.333 ; U23.2@73.119,39.726 73.176,39.782 73.869,39.782 74.393,40.307 v1(74.393,41.254) ; v2(81.954,49.607) 81.966,49.595 U1.N1@82.641,49.595 ; v2(86.362,46.534) 86.392,46.564 86.392,46.919 86.641,47.169 U1.T6@86.641,47.195
  Bottom w0.305: v1(74.403,43.135) 75.235,43.967 C62.1@75.298,43.967 ; v1(75.19,41.276) 75.19,42.259 C124.1@75.298,42.367 ; v1(75.266,46.417) 75.266,45.574 C120.1@75.273,45.568 ; C33.1@80.42,43.241 80.444,43.241 80.743,43.54 80.743,43.938 81.46,44.655 81.46,44.924 v1(81.509,44.972) ; C32.1@80.609,49.455 80.761,49.607 v2(81.954,49.607) ; C67.1@82.186,43.257 82.339,43.41 82.339,44.946 v1(82.366,44.972) ; L4.2@83.922,43.764 84.252,44.094 v1(84.252,44.972) v1@84.252,44.983
  other v1: 74.392,45.32
VDDIO_3V3: C65.1 C68.1 C69.1 C70.1 C71.1 C72.1 C73.1 C74.1 C75.1 C76.1 C77.1 C78.1 C79.1 C80.1 C81.1 C82.1 C83.1 L3.2 TP6.1 U1.B1 U1.E15 U1.G7 U1.G8 U1.G15 U1.H5 U1.J5 U1.J10 U1.K7 U1.K10 U1.R11 U1.T11 U1.T15 | length 40
  Top Layer w0.127: U1.G15@93.841,54.395 94.241,54.795 94.919,54.795 ; U1.E15@93.841,55.995 94.241,56.395 v1(95.42,56.395)
  Top Layer w0.155: U1.T15@93.841,47.195 U1.T15@93.855,47.182 ; v2@93.855,46.535 v2(93.868,46.522)
  Top Layer w0.254: v2(85.441,52.393) 85.441,52.395 U1.J5@85.841,52.795 ; v2@85.441,54.012 v2(85.441,53.995) U1.H5@85.841,53.595 ; v2(87.041,51.595) U1.K7@87.441,51.995 ; v2(87.041,54.795) U1.G7@87.441,54.395 ; v2(87.841,54.795) U1.G8@88.241,54.395 ; U1.K10@89.841,51.995 v2(90.241,51.595) ; U1.J10@89.841,52.795 v2(90.241,52.395)
  Top Layer w0.305: v1(81.356,58.496) 81.425,58.496 81.526,58.395 U1.B1@82.641,58.395 ; v1(81.758,59.824) 81.784,59.798 v1(82.52,59.798) ; U1.R11@90.641,47.995 90.641,43.797 90.928,43.511 v1(90.928,43.492) ; v2@93.855,46.535 U1.T15@93.855,47.182 ; 94.919,54.795 96.52,54.795 97.917,53.398 v1@97.917,53.34
  Bottom w0.254: C77.1@84.602,53.214 85.422,52.393 v2(85.441,52.393) ; v2(85.441,53.995) 85.441,53.799 C71.1@86.029,53.211 ; v2(87.041,54.795) v2(87.841,54.795)
  Bottom w0.305: C72.1@78.304,59.592 C74.1@78.304,60.828 ; C72.1@78.476,59.463 v1(79.47,59.463) ; C76.1@78.68,58.344 78.896,58.344 v1(79.307,58.755) ; C83.1@79.924,47.219 80.06,47.355 80.636,47.355 80.729,47.447 v1(80.797,47.447) ; C68.1@79.927,44.698 80.074,44.846 80.515,44.846 80.678,45.009 v1@80.747,45.009 ; C75.1@79.927,45.976 80.027,45.976 80.174,46.123 80.174,46.223 80.664,46.713 v1(80.876,46.713) ; v1(80.257,59.549) 80.536,59.828 C73.1@80.536,60.829 ; C79.1@80.712,50.902 81.067,50.546 v2(81.94,50.546) ; C69.1@80.841,53.189 81.226,53.189 v2(81.631,53.595) ; v1(81.758,59.824) 81.758,60.8 C81.1@81.79,60.831 ; v1(82.52,59.798) 82.569,59.847 82.569,60.266 83.034,60.731 C80.1@83.034,60.831 ; C70.1@90.2,53.214 90.241,53.172 v2(90.241,52.395) v2(90.241,51.595) ; C78.1@93.865,45.569 C82.1@93.865,47.347 ; v1(100.203,54.381) 101.157,54.381 L3.2@101.292,54.246 ; C65.1@101.41,56.159 101.434,56.159 101.757,56.482 101.757,56.824 102.11,57.178 102.847,57.178 v1(102.895,57.226)
  other v1: 80.747,44.972 97.941,53.396
XDS_CC1: J1.A5 R16.2 U4.4 U4.7 | length 8.6
  Top Layer w0.159: J1.A5@54.192,79.185 58.36,79.185 59.108,78.437 59.101,78.43 59.101,77.596 U4.7@59.094,77.589 U4.4@59.094,76.754
  Bottom w0.127: v1(59.055,78.461) 59.715,77.8 R16.2@59.715,77.025
XDS_CC2: J1.B5 R17.1 U4.5 U4.6 | length 17.4
  Top Layer w0.159: U4.5@59.594,76.754 U4.6@59.594,77.589 59.594,78.084 v1@59.87,78.361
  Bottom w0.127: J1.B5@52.232,77.635 51.562,76.965 51.562,75.895 52.349,75.108 56.236,75.108 58.009,76.882 58.009,78.355 58.623,78.969 59.41,78.969 v1@59.944,78.434 ; v1(60.048,78.384) 60.605,78.384 61.348,77.642 61.348,77.173 R17.1@61.496,77.025
XDS_D_N: J1.A7 J1.B7 U2.93 U4.2 U4.9 | length 17.5
  Top Layer w0.155: J1.B7@52.932,78.835 52.932,78.784 53.477,78.239 54.138,78.239 J1.A7@54.192,78.185 ; v1@55.794,70.976 55.874,71.057 55.874,71.286 57.991,73.403 57.991,76.469 58.094,76.572 U4.2@58.094,76.754 U4.9@58.094,77.589 58.071,77.612 58.071,77.872 57.404,78.539 56.494,78.539 56.462,78.571 56.457,78.571 56.308,78.721 v1(56.198,78.721)
  Bottom w0.155: J1.B7@52.932,78.835 53.024,78.835 53.27,78.589 54.931,78.589 55.063,78.721 v1(56.198,78.721) ; U2.93@53.535,70.666 54.148,70.666 54.192,70.71 55.527,70.71 v1@55.794,70.976
  other v1: 55.827,70.92
XDS_D_P: J1.A6 J1.B6 U2.94 U4.1 U4.10 | length 16.2
  Top Layer w0.155: J1.A6@54.192,78.685 55.198,78.685 v1(55.651,78.232) 57.277,78.232 57.571,77.938 57.571,77.612 U4.10@57.594,77.589 U4.1@57.594,76.754 57.594,76.572 57.684,76.482 57.684,73.53 55.615,71.462 55.364,71.462 v1(55.286,71.385)
  Bottom w0.155: J1.B6@52.932,78.035 53.024,78.035 53.27,78.282 55.602,78.282 v1(55.651,78.232) ; U2.94@53.535,71.066 54.148,71.066 54.196,71.017 54.972,71.017 55.286,71.331 v1(55.286,71.385)
XDS_RESET_OUT: U2.40
XDS_RXD: U2.33 U6.6 | length 8.4
  Top Layer w0.127: v1(66.388,61.501) 66.388,61.968 68.471,64.051 69.435,64.051 U6.6@69.457,64.073
  Bottom w0.127: v1(66.388,61.501) 66.388,61.095 67.435,60.047 U2.33@67.435,57.966
XDS_TCK_SWDCLK: U2.35 U6.5 | length 9.5
  Top Layer w0.127: v1(65.43,61.747) 68.391,64.708 U6.5@69.457,64.708
  Bottom w0.127: v1(65.43,61.747) 65.43,61.221 66.635,60.016 U2.35@66.635,57.966
XDS_TDI: U2.38 U6.2 | length 12.4
  Top Layer w0.127: v1(64.618,63.297) 64.592,63.322 64.592,64.135 67.07,66.613 U6.2@69.457,66.613
  Bottom w0.127: v1(64.618,63.297) 64.618,59.461 65.422,58.657 65.422,57.98 U2.38@65.435,57.966
XDS_TDO_SWO: U2.37 U6.7 | length 7.8
  Top Layer w0.127: v1(65.57,59.703) 66.113,60.246 66.904,61.037 66.904,61.976 68.365,63.438 U6.7@69.457,63.438
  Bottom w0.127: v1(65.57,59.703) 65.57,59.586 65.836,59.32 U2.37@65.835,57.966
XDS_TMS_SWDIO: U2.36 U6.3 | length 11.1
  Top Layer w0.127: v1(66.192,63.932) 66.275,64.014 66.458,64.014 68.421,65.978 U6.3@69.457,65.978
  Bottom w0.127: v1(66.192,63.932) 64.986,62.725 64.986,60.947 66.235,59.698 U2.36@66.235,57.966
XDS_TXD: U2.34 U6.4 | length 9.9
  Top Layer w0.127: v1(65.913,62.865) 68.391,65.343 U6.4@69.457,65.343
  Bottom w0.127: v1(65.913,62.865) 65.913,61.062 67.035,59.939 U2.34@67.035,57.966
pads on no net: B1.7 EC1.4 EC1.13 EC1.16 EC1.29 EC1.32 EC1.41 EC1.43 EC1.44 EC1.66 EC1.113 EC1.114 EC1.115 EC1.116 EC1.117 EC2.136 EC2.171 EC2.172 EC2.173 EC2.174 EC2.175 EC2.176 EC2.177 FID1.1 FID2.1 FID3.1 FID4.1 FID5.1 FID6.1 J1.A2 J1.A3 J1.A8 J1.A10 J1.A11 J1.B2 J1.B3 J1.B8 J1.B10 J1.B11 J3.9 J4.A2 J4.A3 J4.A8 J4.A10 J4.A11 J4.B2 J4.B3 J4.B8 J4.B10 J4.B11 J5.9 J5.ALIGN1 J5.ALIGN2 J6.9 J6.ALIGN1 J6.ALIGN2 S4. U1.G16 U1.H1 U1.J1 U1.J2 U1.K1 U1.K3 U1.K4 U1.L6 U1.N5 U1.N6 U1.N8 U1.P4 U1.P5 U1.P6 U1.P8 U1.R5 U1.R7 U2.1 U2.2 U2.5 U2.6 U2.11 U2.12 U2.13 U2.14 U2.15 U2.18 U2.19 U2.20 U2.21 U2.22 U2.23 U2.24 U2.25 U2.27 U2.29 U2.30 U2.31 U2.32 U2.41 U2.42 U2.43 U2.44 U2.45 U2.46 U2.49 U2.50 U2.53 U2.54 U2.56 U2.57 U2.65 U2.67 U2.71 U2.72 U2.73 U2.74 U2.75 U2.76 U2.77 U2.78 U2.81 U2.82 U2.83 U2.84 U2.85 U2.86 U2.91 U2.92 U2.95 U2.102 U2.103 U2.104 U2.105 U2.106 U2.107 U2.108 U2.109 U2.110 U2.111 U2.112 U2.116 U2.117 U2.118 U2.119 U2.120 U2.121 U2.123 U2.124 U2.125 U2.126 U2.127 U2.128 U4.3@58.594,76.754 U4.8@58.594,77.589 U5.9@79.299,72.238 U5.9@79.299,73.498 U7.3 U7.5 U11.6 U13.3@88.46,71.25 U13.8@88.46,72.085 U17.3@117.725,71.887 U17.8@118.56,71.887 U19.3@117.641,50.618 U19.8@118.476,50.618 U23.1 U23.3 U23.7 U23.8 U24.8 U24.9 U24.16 U25.1 U25.8 U26.1 U26.8

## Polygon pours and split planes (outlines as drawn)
GND on Top Layer "TOP_LAYER_GND_P247" (solid, remove dead copper, pour order 247): 43.681,52.153 67.984,52.153 74.161,58.33 74.161,84.919 149.116,84.919 149.116,35.631 149.116,32.684 148.01,32.684 147.53,32.204 147.53,26.36 122.776,26.36 122.25,26.886 122.25,38.399 105.808,38.399 105.911,38.297 105.911,34.716 106.546,34.208 107.536,34.208 107.536,32.456 107.536,32.204 107.533,32.202 103.042,32.202 103.042,26.259 103.017,26.284 76.853,26.284 76.853,31.665 75.999,32.519 74.884,32.519 74.161,31.795 74.161,26.563 51.199,26.563 51.072,26.436 51.072,32.329 46.704,32.329 46.372,32.66 46.372,34.183 47.948,34.183 48.816,35.051 48.816,39.097 43.681,39.097
5V0 on Top Layer "TOP_LAYER_5V0_P165" (solid, remove dead copper, pour order 165): 80.507,71.112 80.507,68.804 76.426,68.804 76.426,71.112
EMU_3V3 on Top Layer "TOP_LAYER_EMU_3V3_P248" (solid, remove dead copper, pour order 248): 50.317,65.303 59.715,65.303 60.173,64.846 60.173,63.251 50.317,63.251
EMU_5V0 on Top Layer "TOP_LAYER_EMU_5V0_P166" (solid, remove dead copper, pour order 166): 44.142,62.23 50.194,62.23 50.194,68.591 51.136,69.221 51.136,71.391 48.433,71.391 48.433,76.463 47.858,77.038 44.116,77.038
POWER_SWITCH_OUT on Top Layer "TOP_LAYER_POWER_SWITCH_OUT_P239" (solid, remove dead copper, pour order 239): 74.133,75.794 77.622,75.794 77.622,68.817 74.133,68.817
NetT1_4 on Top Layer "TOP_LAYER_NETT1_4_P167" (solid, remove dead copper, pour order 167): 61.011,82.652 65.354,82.652 65.761,82.245 65.761,80.975 65.481,80.696 63.119,80.696 62.205,81.61 62.189,81.594 60.951,81.594 60.757,81.788 60.757,82.398
NetT1_6 on Top Layer "TOP_LAYER_NETT1_6_P169" (solid, remove dead copper, pour order 169): 60.858,80.772 62.281,80.772 62.535,80.518 62.535,77.953 63.271,77.216 66.192,77.216 66.497,76.911 66.497,75.616 66.204,75.322 61.355,75.322 60.649,76.029 60.649,80.562
EMU_5V0 on Top Layer "TOP_LAYER_EMU_5V0_P204" (solid, remove dead copper, pour order 204): 52.654,79.985 52.705,80.035 54.889,80.035 54.889,81.458 55.626,82.194 56.845,82.194 57.633,81.407 57.633,79.451 57.607,79.451 57.48,79.324 54.788,79.324 54.661,79.451 54.654,79.444 53.358,79.444 53.162,79.248 52.603,79.248 52.603,79.959 52.629,79.985
EMU_5V0 on Top Layer "TOP_LAYER_EMU_5V0_P170" (solid, remove dead copper, pour order 170): 52.857,77.775 56.921,77.775 57.328,77.368 57.328,75.743 56.947,75.362 55.27,75.362 54.915,75.717 54.915,76.886 54.839,76.962 54.813,76.937 52.578,76.937 52.578,77.495 52.629,77.546
ISO_Pout_5V0 on Top Layer "TOP_LAYER_ISO_POUT_5V0_P210" (solid, remove dead copper, pour order 210): 82.038,84.64 82.038,75.521 78.583,75.521 78.583,84.64
NetD1:A_2 on Top Layer "TOP_LAYER_NETD1:A_2_P211" (solid, remove dead copper, pour order 211): 74.189,77.352 78.583,77.352 78.583,75.318 74.189,75.318
NetD2:A_2 on Top Layer "TOP_LAYER_NETD2:A_2_P216" (solid, remove dead copper, pour order 216): 74.189,80.982 76.475,80.982 77.136,81.835 78.426,81.835 78.426,84.69 74.189,84.69
EMU_3V3 on Top Layer "TOP_LAYER_EMU_3V3_P238" (solid, remove dead copper, pour order 238): 50.261,69.113 54.935,69.113 54.935,63.576 50.261,63.576
EMU_GND on Top Layer "Top Layer-EMU_GND" (solid, remove dead copper, pour order 240): 45.514,56.278 55.238,56.278 57.29,58.799 65.351,58.799 65.351,59.687 65.176,59.687 65.176,61.384 60.295,61.384 60.295,60.698 45.514,60.698
VDDIO_3V3 on Power 4 "POWER_4_VDDIO_3V3_P183" (solid, remove dead copper, pour order 183): 86.395,52.152 87.154,52.152 87.328,51.979 87.328,51.271 86.442,51.271 86.434,51.263
VDD_1V2 on Power 4 "POWER_4_VDD_1V2_P185" (solid, remove dead copper, pour order 185): 90.597,52.744 91.492,52.744 91.573,52.664 91.566,52.657 91.566,52.158 91.531,52.123 90.6,52.123
VDDIO_3V3 on Power 4 "POWER_4_VDDIO_3V3_P184" (solid, remove dead copper, pour order 184): 89.808,52.744 90.597,52.744 90.597,52.009 90.705,51.9 90.705,51.297 90.67,51.261 89.814,51.261
VDD_1V2 on Power 4 "POWER_4_VDD_1V2_P187" (solid, remove dead copper, pour order 187): 87.359,52.034 87.365,52.04 89.657,52.04 89.657,51.342 89.545,51.23 87.563,51.23 87.387,51.406
VDDIO_3V3 on Power 4 "POWER_4_VDDIO_3V3_P226" (solid, remove dead copper, pour order 226): 86.766,55.198 88.408,55.198 88.408,54.592 88.067,54.251 86.766,54.251
VDD_1V2 on Power 4 "POWER_4_VDD_1V2_P213" (solid, remove dead copper, pour order 213): 85.779,55.201 86.635,55.201 86.635,54.35 85.779,54.35
VDDIO_3V3 on Power 4 "POWER_4_VDDIO_3V3_P243" (solid, remove dead copper, pour order 243): 77.778,68.402 88.417,68.402 88.417,54.602 88.066,54.251 86.56,54.251 86.56,55.065 86.413,55.212 86.393,55.193 85.641,55.193 85.641,53.573 86.326,52.888 86.891,52.888 86.891,51.844 87.639,51.096 89.643,51.096 89.808,51.262 89.808,52.696 90.597,52.696 90.597,52.009 93.961,52.009 94.306,52.354 94.306,56.801 95.353,57.848 102.391,57.848 104.038,56.201 104.446,56.201 104.771,55.876 104.771,45.919 99.895,41.043 78.235,41.043 77.778,41.537
5V0 on Power 4 "POWER_4_5V0_P253" (solid, remove dead copper, pour order 253): 83.582,85.173 83.638,83.007 83.638,80.558 80.175,77.096 77.782,74.703 77.816,68.402 88.553,68.402 88.553,79.894 94.463,79.911 94.463,75.254 102.434,75.254 102.434,78.848 103.274,79.688 106.931,79.688 107.017,75.131 131.332,74.944 137.257,69.019 137.257,60.405 131.215,60.405 130.91,38.513 149.018,38.513 149.018,84.843 148.687,85.173
EMU_5V0 on Power 4 "POWER_4_EMU_5V0_P251" (solid, remove dead copper, pour order 251): 44.306,84.741 66.595,84.741 66.595,77.756 64.537,75.699 56.69,75.699 50.013,69.021 50.013,62.738 49.149,61.874 44.856,61.874 44.348,62.382 44.351,62.385 44.351,84.658
USB_5V0 on Power 4 "POWER_4_USB_5V0_P244" (solid, remove dead copper, pour order 244): 88.697,79.818 94.09,79.818 94.459,79.449 94.406,79.396 94.406,65.219 94.018,64.832 88.697,64.832
3V3 on Power 4 "POWER_4_3V3_P250" (solid, remove dead copper, pour order 250): 105.715,61.722 104.984,62.453 104.984,64.771 107.728,67.514 107.721,67.52 107.721,74.78 108.507,75.566 130.71,75.566 137.283,68.993 137.283,60.833 137.192,60.833 136.73,60.37 131.781,60.37 130.429,61.722 105.435,61.722
1V2 on Power 4 "POWER_4_1V2_P249" (solid, remove dead copper, pour order 249): 104.39,61.276 105.025,61.912 130.239,61.912 131.318,60.833 131.318,38.921 130.878,38.481 126.848,38.481 126.304,39.025 126.304,47.814 122.254,51.863 122.221,51.83 105.273,51.83 104.857,52.246 104.857,58.414 104.39,58.881
VDD_1V2 on Power 4 "POWER_4_VDD_1V2_P245" (solid, remove dead copper, pour order 245): 85.494,55.201 86.553,55.201 86.553,54.504 88.353,54.504 88.353,65.224 94.367,65.224 94.367,75.265 102.075,75.265 102.075,79.273 102.779,79.977 106.8,79.977 107.505,79.272 107.505,67.525 104.762,64.782 104.762,55.296 102.118,55.296 102.118,57.955 95.351,57.955 94.306,56.82 94.306,51.999 90.39,51.999 90.39,52.748 89.736,52.748 89.736,51.225 87.217,51.225 87.217,52.667 85.494,53.445
EMU_3V3 on Power 4 "POWER_4_EMU_3V3_P252" (solid, remove dead copper, pour order 252): 44.14,84.894 70.452,84.894 70.452,60.023 66.391,55.963 44.015,55.963
HSEC_5V0 on Power 4 "POWER_4_HSEC_5V0_P254" (solid, remove dead copper, pour order 254): 74.207,84.775 83.642,84.796 83.642,80.158 77.876,74.392 77.876,41.228 90.674,41.228 93.848,44.403 102.888,44.403 104.776,46.291 104.776,52.483 121.828,52.483 126.437,47.875 126.437,38.488 130.399,38.488 148.654,38.434 148.865,26.626 149.195,26.956 144.471,26.804 122.821,27.042 122.703,37.802 122.227,38.895 106.187,38.895 107.43,32.983 102.888,32.906 102.967,26.436 79.967,26.436 80.793,26.436 44.166,26.436 44.166,52.178 46.071,52.178 67.958,52.178 74.207,58.427
GND on Bottom "BOTTOM_GND_P235" (solid, remove dead copper, pour order 235): 43.681,52.153 67.984,52.153 74.161,58.33 74.161,84.919 149.116,84.919 149.116,35.631 149.116,32.684 148.01,32.684 147.53,32.204 147.53,26.886 122.25,26.886 122.25,38.399 105.808,38.399 105.911,38.297 105.911,34.716 106.546,34.208 107.536,34.208 107.536,32.456 107.536,32.204 107.533,32.202 103.042,32.202 103.042,26.259 103.017,26.284 76.853,26.284 76.853,31.665 75.999,32.519 74.884,32.519 74.161,31.795 74.161,26.563 51.199,26.563 51.072,26.436 51.072,32.329 46.704,32.329 46.704,34.183 47.948,34.183 48.816,35.051 48.816,39.097 43.681,39.097
EMU_3V3 on Bottom "BOTTOM_EMU_3V3_P234" (solid, remove dead copper, pour order 234): 52.781,68.453 52.781,64.25 49.759,64.25 49.759,68.453
NetC48_2 on Bottom "BOTTOM_NETC48_2_P219" (solid, remove dead copper, pour order 219): 129.637,45.153 130.928,45.153 130.928,44.846 131.732,44.042 134.483,44.042 134.483,42.627 134.628,42.536 140.26,42.542 140.26,43.573 140.309,43.622 142.108,43.622 142.108,42.659 141.985,42.536 140.981,42.536 140.981,40.335 141.004,40.312 140.85,40.158 134.565,40.158 134.25,40.473 134.25,41.407 133.925,41.732 130.2,41.732 129.637,42.295
NetC50_2 on Bottom "BOTTOM_NETC50_2_P203" (solid, remove dead copper, pour order 203): 129.794,52.561 129.794,51.148 130.564,51.148 131.805,49.906 134.503,49.906 134.503,51.435 140.868,51.435 140.868,52.275 140.981,52.387 142.035,52.387 142.035,51.533 142.231,51.533 143.235,51.533 143.235,53.513 142.9,53.848 134.503,53.848 134.503,52.188 132.038,52.188 131.665,52.561
NetL2_1 on Bottom "BOTTOM_NETL2_1_P194" (solid, remove dead copper, pour order 194): 139.192,49.276 138.043,49.276 137.273,48.506 137.273,47.527 136.746,47.527 136.746,49.033 136.045,49.733 134.645,49.733 134.645,51.46 139.192,51.46
NetL1_1 on Bottom "BOTTOM_NETL1_1_P222" (solid, remove dead copper, pour order 222): 136.189,44.316 136.804,44.932 136.804,46.431 137.097,46.431 137.103,46.437 137.225,46.315 137.225,45.88 138.604,44.501 139.294,44.501 139.294,42.748 136.189,42.748
5V0 on Bottom "BOTTOM_5V0_P225" (solid, remove dead copper, pour order 225): 131.673,45.751 131.673,46.85 133.198,46.85 133.198,46.247 135.978,46.247 136.694,46.247 136.694,44.821 136.047,44.174 131.673,44.174
5V0 on Bottom "BOTTOM_5V0_P229" (solid, remove dead copper, pour order 229): 132.559,49.764 132.559,48.158 134.645,48.158 135.814,48.158 136.259,47.713 136.788,47.713 136.788,49.277 136.301,49.764
5V0 on Bottom "BOTTOM_5V0_P230" (solid, remove dead copper, pour order 230): 148.626,50.081 145.807,50.081 145.807,47.033 148.626,47.033
EMU_5V0 on Bottom "BOTTOM_EMU_5V0_P231" (solid, remove dead copper, pour order 231): 59.565,81.708 59.818,81.708 61.022,81.708 61.022,81.481 62.383,81.481 62.383,81.007 66.493,81.007 66.493,78.086 61.235,78.086 59.565,79.757
5V0 on Bottom "BOTTOM_5V0_P232" (solid, remove dead copper, pour order 232): 82.098,84.817 82.098,82.093 85.903,82.093 87.953,80.042 97.055,80.042 97.055,84.817
EMU_GND on GND 2 "GND_2_EMU_GND_P206" (solid, remove dead copper, pour order 206): 44.329,85.008 70.532,85.008 70.532,60.078 66.417,55.963 44.273,55.963
ETH1_EARTH on GND 2 "GND_2_ETH1_EARTH_P172" (solid, remove dead copper, pour order 172): 138.836,81.991 138.887,82.042 142.824,82.042 142.824,84.654 142.82,84.658 142.876,84.715 148.635,84.715 148.635,33.972 148.578,33.916 141.004,33.916 141.004,40.592 143.049,40.592 143.049,43.913 143.039,43.922 143.037,43.921 126.57,43.921 126.57,45.873 142.972,45.873 142.972,55.544 140.915,57.602 140.777,57.602 140.777,61.742 142.682,63.647 142.682,65.884 142.545,66.021 126.57,66.021 126.57,68.485 142.82,68.485 142.82,78.112 142.792,78.083 138.843,78.083 138.843,82.023 138.862,82.042
GND on GND 2 "GND_2_GND_P227" (solid, remove dead copper, pour order 227): 44.2,52.086 44.22,52.107 67.938,52.107 73.985,58.56 74.28,85.347 142.946,85.242 142.946,78.083 142.946,68.44 126.867,68.44 126.867,65.987 143.32,65.987 143.32,63.954 141.211,61.845 141.211,57.568 143.28,55.499 143.28,46.162 142.946,45.828 126.867,45.828 126.867,43.887 143.345,43.887 143.345,40.467 141.315,40.467 141.315,39.264 143.636,36.944 148.843,36.944 149.148,36.639 149.148,33.134 148.682,32.668 147.421,32.668 147.421,26.961 123.087,26.961 123.087,38.221 122.191,39.117 106.439,39.117 105.841,38.518 105.841,34.708 106.603,33.946 107.72,33.946 107.72,32.668 103.159,32.668 103.159,26.809 77.317,26.809 77.317,32.013 76.349,32.981 75.234,32.981 74.218,31.965 74.218,26.975 51.561,26.961 51.561,32.524 47.09,32.524 47.09,33.26 47.09,34.048 48.341,34.048 48.856,34.563 48.856,39.117 44.22,39.077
